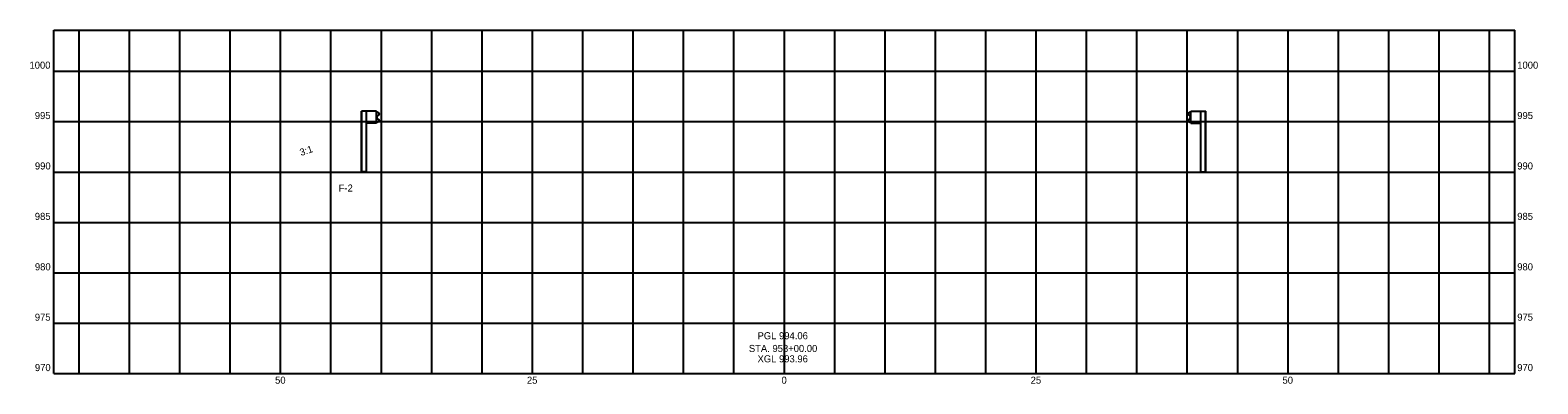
# Model space of a CAD drawing. Extents: x -75 to 75, y 969 to 1004.
import ezdxf

# ---------------------------------------------------------------- set-up
doc = ezdxf.new("R2010")
doc.units = 0
for name, color, linetype in [('RD_P_Cells', 7, 'Continuous'), ('SH_Major_Grid_Line', 7, 'Continuous'), ('SH_Text', 7, 'Continuous')]:
    doc.layers.add(name, color=color, linetype=linetype)

msp = doc.modelspace()

# ---------------------------------------------------------------- linework, layer by layer
at = {"layer": 'RD_P_Cells'}
for p, q in [((-41.48, 996.02), (-41.96, 996.02)), ((-41.96, 990.02), (-41.96, 996.02)), ((-41.94, 990.02), (-41.94, 996.02)), ((-40.48, 996.02), (-41.48, 996.02)), ((-41.48, 994.85), (-41.48, 996.02)), ((-41.48, 994.85), (-41.48, 996.02)), ((-41.46, 994.85), (-41.46, 996.02)), ((-40.48, 994.85), (-40.48, 996.02)), ((-40.47, 995.95), (-40.47, 995.95)), ((-40.47, 995.95), (-40.38, 995.93)), ((-40.47, 995.94), (-40.47, 995.95)), ((-40.47, 995.94), (-40.47, 995.94)), ((-40.38, 995.92), (-40.47, 995.94)), ((-40.47, 995.48), (-40.47, 995.48)), ((-40.47, 995.39), (-40.47, 995.48)), ((-40.47, 995.4), (-40.47, 995.47)), ((-40.47, 995.39), (-40.47, 995.39)), ((-40.46, 995.48), (-40.46, 995.48)), ((-40.46, 995.48), (-40.46, 995.39)), ((-40.46, 995.4), (-40.46, 995.47)), ((-40.46, 995.39), (-40.46, 995.39)), ((-40.43, 995.55), (-40.24, 995.69)), ((-40.43, 995.55), (-40.43, 995.55)), ((-40.43, 995.32), (-40.43, 995.32)), ((-40.24, 995.18), (-40.43, 995.32)), ((-40.24, 995.68), (-40.42, 995.55)), ((-40.42, 995.55), (-40.42, 995.55)), ((-40.42, 995.33), (-40.42, 995.33)), ((-40.42, 995.33), (-40.24, 995.19)), ((-40.38, 995.93), (-40.38, 995.93)), ((-40.38, 995.93), (-40.24, 995.83)), ((-40.38, 995.92), (-40.38, 995.92)), ((-40.24, 995.82), (-40.38, 995.92)), ((-40.36, 995.91), (-40.36, 995.91)), ((-40.36, 995.91), (-40.36, 995.91)), ((-40.36, 995.6), (-40.36, 995.6)), ((-40.36, 995.59), (-40.36, 995.59)), ((-40.24, 995.83), (-40.24, 995.83)), ((-40.24, 995.82), (-40.24, 995.82)), ((-40.24, 995.69), (-40.24, 995.69)), ((-40.24, 995.68), (-40.24, 995.68)), ((-40.21, 995.75), (-40.21, 995.75)), ((-40.2, 995.75), (-40.2, 995.75)), ((40.07, 995.75), (40.07, 995.75)), ((40.08, 995.75), (40.08, 995.75)), ((40.25, 995.93), (40.11, 995.82)), ((40.11, 995.82), (40.25, 995.92)), ((40.11, 995.82), (40.11, 995.82)), ((40.11, 995.82), (40.11, 995.82)), ((40.11, 995.69), (40.11, 995.69)), ((40.3, 995.55), (40.11, 995.69)), ((40.11, 995.68), (40.11, 995.68)), ((40.11, 995.68), (40.29, 995.54)), ((40.11, 995.18), (40.3, 995.32)), ((40.29, 995.32), (40.11, 995.19)), ((40.23, 995.91), (40.23, 995.91)), ((40.23, 995.9), (40.23, 995.9)), ((40.23, 995.6), (40.23, 995.6)), ((40.23, 995.59), (40.23, 995.59)), ((40.34, 995.95), (40.25, 995.93)), ((40.25, 995.92), (40.34, 995.94)), ((40.25, 995.93), (40.25, 995.93)), ((40.25, 995.92), (40.25, 995.92)), ((40.29, 995.54), (40.29, 995.54)), ((40.29, 995.32), (40.29, 995.32)), ((40.3, 995.55), (40.3, 995.55)), ((40.3, 995.32), (40.3, 995.32)), ((40.33, 995.48), (40.33, 995.48)), ((40.33, 995.48), (40.33, 995.39)), ((40.33, 995.4), (40.33, 995.46)), ((40.33, 995.39), (40.33, 995.39)), ((40.34, 995.95), (40.34, 995.95)), ((40.34, 995.94), (40.34, 995.95)), ((40.34, 995.94), (40.34, 995.94)), ((40.34, 995.48), (40.34, 995.48)), ((40.34, 995.39), (40.34, 995.48)), ((40.34, 995.4), (40.34, 995.46)), ((40.34, 995.39), (40.34, 995.39)), ((40.35, 996.02), (41.35, 996.02)), ((40.35, 994.85), (40.35, 996.02)), ((41.33, 994.85), (41.33, 996.02)), ((41.35, 996.02), (41.83, 996.02)), ((41.35, 994.85), (41.35, 996.02)), ((41.35, 994.85), (41.35, 996.02)), ((41.81, 990.02), (41.81, 996.02)), ((41.83, 990.02), (41.83, 996.02)), ((-40.48, 994.85), (-41.48, 994.85)), ((-41.48, 990.02), (-41.48, 994.85)), ((-41.46, 990.02), (-41.46, 994.85)), ((-40.46, 994.93), (-40.38, 994.95)), ((-40.38, 994.94), (-40.46, 994.92)), ((-40.46, 994.93), (-40.46, 994.93)), ((-40.46, 994.92), (-40.46, 994.93)), ((-40.46, 994.92), (-40.46, 994.92)), ((-40.38, 994.95), (-40.24, 995.05)), ((-40.23, 995.05), (-40.38, 994.94)), ((-40.24, 995.19), (-40.24, 995.19)), ((-40.24, 995.18), (-40.24, 995.18)), ((-40.24, 995.05), (-40.24, 995.05)), ((-40.23, 995.05), (-40.23, 995.05)), ((-40.21, 995.12), (-40.21, 995.12)), ((-40.2, 995.12), (-40.2, 995.12)), ((40.07, 995.12), (40.07, 995.12)), ((40.08, 995.12), (40.08, 995.12)), ((40.1, 995.04), (40.1, 995.04)), ((40.1, 995.04), (40.25, 994.94)), ((40.11, 995.19), (40.11, 995.19)), ((40.11, 995.18), (40.11, 995.18)), ((40.11, 995.05), (40.11, 995.05)), ((40.25, 994.95), (40.11, 995.05)), ((40.33, 994.93), (40.25, 994.95)), ((40.25, 994.94), (40.33, 994.92)), ((40.33, 994.93), (40.33, 994.93)), ((40.33, 994.92), (40.33, 994.93)), ((40.33, 994.92), (40.33, 994.92)), ((40.35, 994.85), (41.35, 994.85)), ((41.33, 990.02), (41.33, 994.85)), ((41.35, 990.02), (41.35, 994.85)), ((-41.46, 990.02), (-41.96, 990.02)), ((41.33, 990.02), (41.83, 990.02))]:
    msp.add_line(p, q, dxfattribs=at)
for points in [[(-40.45, 995.5), (-40.45, 995.38), (-40.46, 995.38), (-40.46, 995.5)], [(-40.45, 995.46), (-40.45, 995.41), (-40.42, 995.41), (-40.42, 995.46)], [(40.32, 995.46), (40.32, 995.4), (40.29, 995.4), (40.29, 995.46)], [(40.32, 995.49), (40.32, 995.37), (40.33, 995.37), (40.33, 995.49)]]:
    msp.add_lwpolyline(points, close=True, dxfattribs=at)
for centre, radius, start, end in [((-40.38, 995.48), 0.0886, 126.318, 180.0944), ((-40.38, 995.39), 0.0886, 180.0944, 233.8707), ((-40.38, 995.48), 0.0788, 126.318, 180.0944), ((-40.38, 995.39), 0.0788, 180.0944, 233.8707), ((-40.29, 995.75), 0.0886, 306.318, 53.2212), ((-40.29, 995.75), 0.0787, 306.318, 53.2212), ((40.16, 995.75), 0.0886, 126.7788, 233.682), ((40.16, 995.75), 0.0787, 126.7788, 233.682), ((40.25, 995.48), 0.0788, 359.9056, 53.682), ((40.25, 995.39), 0.0788, 306.1293, 359.9056), ((40.25, 995.48), 0.0886, 359.9056, 53.682), ((40.25, 995.39), 0.0886, 306.1293, 359.9056), ((-40.29, 995.12), 0.0886, 306.9675, 53.8707), ((-40.29, 995.12), 0.0787, 306.9675, 53.8707), ((40.16, 995.12), 0.0886, 126.1293, 233.0325), ((40.16, 995.12), 0.0787, 126.1293, 233.0325)]:
    msp.add_arc(centre, radius, start, end, dxfattribs=at)
at = {"layer": 'SH_Major_Grid_Line'}
for p, q in [((-72.5, 1004.07), (72.5, 1004.07)), ((-72.5, 970), (-72.5, 1004.07)), ((-70, 970), (-70, 1004.07)), ((-65, 970), (-65, 1004.07)), ((-60, 970), (-60, 1004.07)), ((-55, 970), (-55, 1004.07)), ((-50, 970), (-50, 1004.07)), ((-45, 970), (-45, 1004.07)), ((-40, 970), (-40, 1004.07)), ((-35, 970), (-35, 1004.07)), ((-30, 970), (-30, 1004.07)), ((-25, 970), (-25, 1004.07)), ((-20, 970), (-20, 1004.07)), ((-15, 970), (-15, 1004.07)), ((-10, 970), (-10, 1004.07)), ((-5, 970), (-5, 1004.07)), ((0, 970), (0, 1004.07)), ((5, 970), (5, 1004.07)), ((10, 970), (10, 1004.07)), ((15, 970), (15, 1004.07)), ((20, 970), (20, 1004.07)), ((25, 970), (25, 1004.07)), ((30, 970), (30, 1004.07)), ((35, 970), (35, 1004.07)), ((40, 970), (40, 1004.07)), ((45, 970), (45, 1004.07)), ((50, 970), (50, 1004.07)), ((55, 970), (55, 1004.07)), ((60, 970), (60, 1004.07)), ((65, 970), (65, 1004.07)), ((70, 970), (70, 1004.07)), ((72.5, 970), (72.5, 1004.07)), ((-72.5, 1000), (72.5, 1000)), ((-72.5, 995), (72.5, 995)), ((-72.5, 990), (72.5, 990)), ((-72.5, 985), (72.5, 985)), ((-72.5, 980), (72.5, 980)), ((-72.5, 975), (72.5, 975)), ((-72.5, 970), (72.5, 970))]:
    msp.add_line(p, q, dxfattribs=at)

# ---------------------------------------------------------------- texts
at = {"layer": 'SH_Text'}
for s, p in [('1000', (-74.93, 1000.25)), ('1000', (72.75, 1000.25)), ('995', (-74.4, 995.25)), ('995', (72.75, 995.25)), ('990', (-74.39, 990.25)), ('990', (72.75, 990.25)), ('F-2', (-44.24, 988.06)), ('985', (-74.4, 985.25)), ('985', (72.75, 985.25)), ('980', (-74.39, 980.25)), ('980', (72.75, 980.25)), ('975', (-74.4, 975.25)), ('975', (72.75, 975.25)), ('STA. 953+00.00', (-3.52, 972.15)), ('PGL 994.06', (-2.66, 973.41)), ('XGL 993.96', (-2.66, 971.12)), ('970', (-74.39, 970.25)), ('970', (72.75, 970.25)), ('50', (-50.55, 969)), ('25', (-25.55, 969)), ('0', (-0.28, 969)), ('25', (24.45, 969)), ('50', (49.45, 969))]:
    msp.add_text(s, height=0.7, dxfattribs=at).set_placement(p)
msp.add_text('3:1', height=0.7, rotation=18.4315, dxfattribs=at).set_placement((-47.97, 991.58))

doc.saveas('drawing.dxf')
